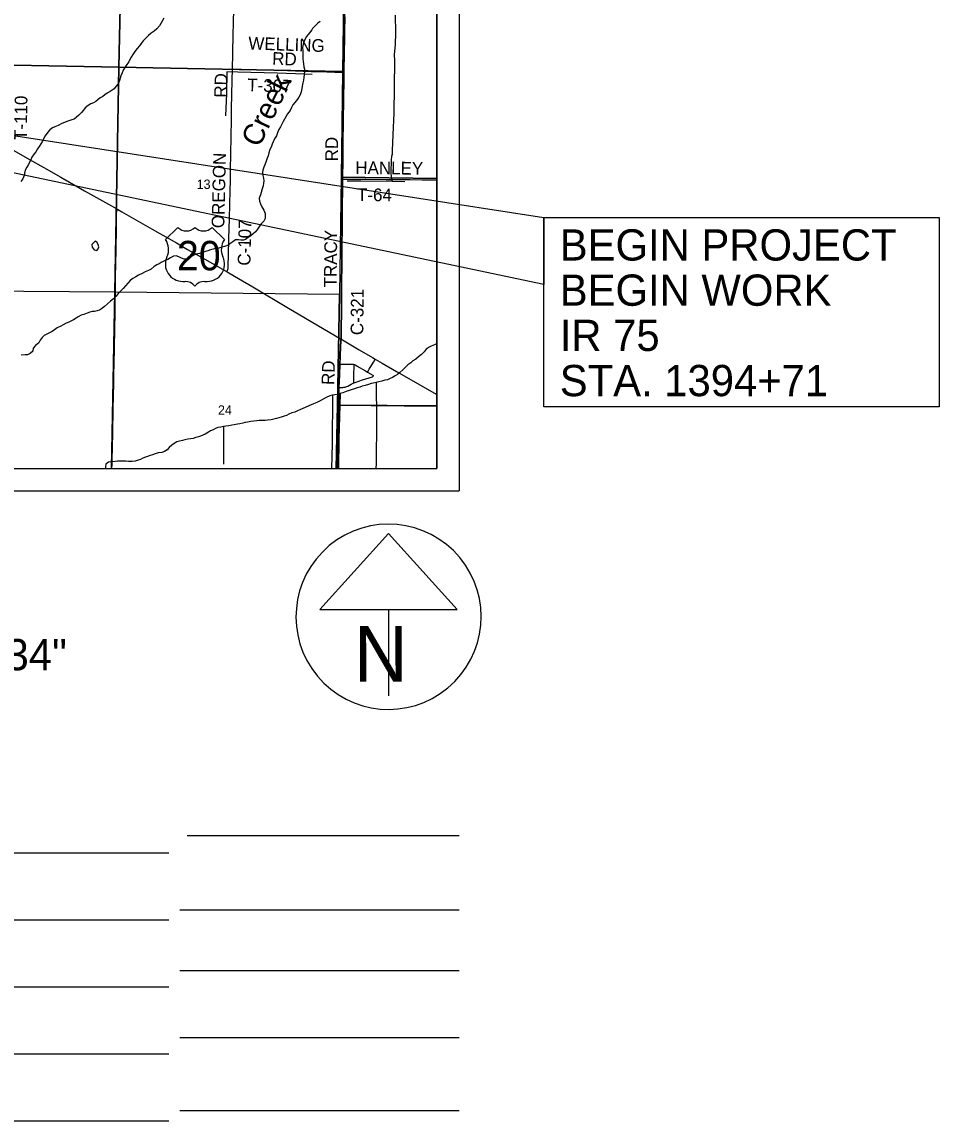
# Model space of a CAD drawing. Extents: x 0 to 34, y 0 to 22.
# Drawn here: x 7.043 to 11.15, y 11.177 to 16.1 of the extents above; entities that cross this region are included whole.
import ezdxf

# ---------------------------------------------------------------- set-up
doc = ezdxf.new("R2010")
doc.units = 0
for name, color, linetype in [('GM_X_Corporation', 7, 'Continuous'), ('GM_X_County_Road', 7, 'Continuous'), ('GM_X_County_Road_Text', 7, 'Continuous'), ('GM_X_Minor_Lake', 7, 'Continuous'), ('GM_X_Minor_River', 7, 'Continuous'), ('GM_X_Minor_River_Text', 7, 'Continuous'), ('GM_X_Section_Text', 7, 'Continuous'), ('GM_X_Township_Road', 7, 'Continuous'), ('GM_X_Township_Road_Text', 7, 'Continuous'), ('GM_X_US_Location', 7, 'Continuous'), ('GM_X_US_Route', 7, 'Continuous'), ('GM_X_US_Shield', 7, 'Continuous'), ('SH_Data', 7, 'Continuous'), ('SH_Text', 7, 'Continuous')]:
    doc.layers.add(name, color=color, linetype=linetype)

msp = doc.modelspace()

# ---------------------------------------------------------------- linework, layer by layer
at = {"layer": 'GM_X_Corporation'}
for points in [[(2.1, 14.1), (8.9, 14.1), (8.9, 20.9), (5.8906, 20.9)], [(8.4889, 16.1222), (8.4875, 16.0575), (8.4871, 16.0295), (8.4858, 15.9593), (8.4845, 15.8803), (8.4844, 15.8737), (8.4837, 15.8337), (8.4828, 15.7634), (8.4812, 15.6466), (8.4803, 15.5676), (8.4796, 15.5203), (8.4791, 15.4756), (8.4782, 15.4066), (8.4781, 15.3967), (8.4781, 15.3506), (8.4774, 15.2729), (8.4769, 15.2262), (8.4765, 15.1622), (8.4758, 15.1118), (8.4752, 15.0167), (8.4743, 14.924), (8.4737, 14.8656), (8.4731, 14.7904), (8.4726, 14.7381), (8.4723, 14.7071), (8.4716, 14.6802), (8.4711, 14.6716), (8.4707, 14.6634), (8.4699, 14.651), (8.4677, 14.5982), (8.4663, 14.568), (8.4663, 14.5671), (8.4642, 14.5205), (8.4627, 14.4863), (8.462, 14.4645), (8.462, 14.463), (8.4613, 14.4241), (8.4606, 14.3899), (8.4605, 14.3826), (8.9, 14.3789), (8.9, 20.9)], [(2.3741, 14.1), (8.4543, 14.1), (8.4553, 14.1598), (8.4566, 14.2158), (8.4581, 14.2655), (8.4592, 14.3153), (8.46, 14.3464), (8.4605, 14.3826), (8.4606, 14.3899), (8.4613, 14.4241), (8.462, 14.463), (8.462, 14.4645), (8.4627, 14.4863), (8.4642, 14.5205), (8.4663, 14.5671), (8.4663, 14.568), (8.4677, 14.5982), (8.4699, 14.651), (8.4707, 14.6634), (8.4711, 14.6716), (8.4716, 14.6802), (8.4723, 14.7071), (8.4726, 14.7381), (8.4731, 14.7904), (8.4737, 14.8656), (8.4743, 14.924), (8.4752, 15.0167), (8.4758, 15.1118), (8.4765, 15.1622), (8.4769, 15.2262), (8.4774, 15.2729), (8.4781, 15.3506), (8.4781, 15.3967), (8.4782, 15.4066), (8.4791, 15.4756), (8.4796, 15.5203), (8.4803, 15.5676), (8.4812, 15.6466), (8.4828, 15.7634), (8.4837, 15.8337), (8.4844, 15.8737), (8.4845, 15.8803), (8.4858, 15.9593), (8.4871, 16.0295), (8.4875, 16.0575), (8.4889, 16.1222)]]:
    msp.add_lwpolyline(points, dxfattribs=at)
for points in [[(6.4745, 16.9262), (7.4991, 16.9078), (7.4758, 15.8976), (6.4581, 15.916)], [(7.4991, 16.9078), (8.4956, 16.8828), (8.4859, 16.4125), (8.4788, 15.8782), (7.4758, 15.8976)], [(8.9, 15.399), (8.9, 16.4075), (8.4859, 16.4125), (8.4788, 15.8782), (8.4721, 15.4049)], [(6.4581, 15.916), (7.4758, 15.8976), (7.4587, 14.8897), (6.4397, 14.8975)], [(7.4758, 15.8976), (8.4788, 15.8782), (8.4721, 15.4049), (8.4652, 14.8797), (7.4587, 14.8897)], [(8.9, 14.3806), (8.9, 15.399), (8.4721, 15.4049), (8.4652, 14.8797), (8.4556, 14.3834)], [(6.4222, 14.1), (7.4432, 14.1), (7.4587, 14.8897), (6.4397, 14.8975)], [(7.4432, 14.1), (8.4504, 14.1), (8.4556, 14.3834), (8.4652, 14.8797), (7.4587, 14.8897)], [(8.4504, 14.1), (8.9, 14.1), (8.9, 14.3806), (8.4556, 14.3834)], [(8.4543, 14.1), (8.9, 14.1), (8.9, 14.3789), (8.4605, 14.3826), (8.46, 14.3464), (8.4592, 14.3153), (8.4581, 14.2655), (8.4566, 14.2158), (8.4553, 14.1598)]]:
    msp.add_lwpolyline(points, close=True, dxfattribs=at)
at = {"layer": 'GM_X_County_Road'}
for points in [[(7.9851, 15.8887), (7.9866, 15.9593), (7.9884, 16.0454), (7.9898, 16.0926), (7.9932, 16.2305), (7.9946, 16.2726), (7.9962, 16.3398), (7.9972, 16.3958)], [(8.4846, 15.8731), (8.4847, 15.8798), (8.4861, 15.9587), (8.4873, 16.029), (8.4877, 16.057), (8.4891, 16.1216), (8.49, 16.1701), (8.4912, 16.2267), (8.4918, 16.2553), (8.4924, 16.2975), (8.4928, 16.3274), (8.4933, 16.3653), (8.4935, 16.3796)], [(7.9613, 14.9807), (7.9638, 14.9881), (7.9648, 14.9911), (7.9655, 14.9948), (7.966, 14.9985), (7.9662, 15.0024), (7.9664, 15.0083), (7.9674, 15.0557), (7.9694, 15.1288), (7.9717, 15.219), (7.9747, 15.3448), (7.9759, 15.3877), (7.9768, 15.4449), (7.9778, 15.5009), (7.9793, 15.5947), (7.9805, 15.6532), (7.9813, 15.7128), (7.9826, 15.7731), (7.984, 15.8391), (7.9851, 15.8887)], [(8.4784, 15.3961), (8.4784, 15.406), (8.4793, 15.475), (8.4798, 15.5198), (8.4805, 15.567), (8.4814, 15.646), (8.4831, 15.7629), (8.4839, 15.8332), (8.4846, 15.8731)], [(8.4719, 14.6796), (8.4726, 14.7065), (8.4728, 14.7376), (8.4733, 14.7898), (8.4739, 14.8651), (8.4745, 14.9235), (8.4754, 15.0161), (8.476, 15.1113), (8.4767, 15.1616), (8.4772, 15.2257), (8.4776, 15.2723), (8.4783, 15.35), (8.4784, 15.3961)]]:
    msp.add_lwpolyline(points, dxfattribs=at)
at = {"layer": 'GM_X_Minor_Lake'}
msp.add_line((7.3863, 15.093), (7.3834, 15.1037), dxfattribs=at)
msp.add_lwpolyline([(7.3834, 15.1037), (7.3782, 15.114), (7.3711, 15.1179), (7.3562, 15.1033), (7.3571, 15.0911), (7.3657, 15.0789), (7.3774, 15.0768), (7.3839, 15.084), (7.3863, 15.093)], dxfattribs=at)
at = {"layer": 'GM_X_Minor_River'}
msp.add_line((8.9, 15.3795), (8.8999, 15.3795), dxfattribs=at)
for points in [[(7.6776, 16.1167), (7.6652, 16.0926), (7.6587, 16.0821), (7.6464, 16.0689), (7.6342, 16.0588), (7.6208, 16.0495), (7.609, 16.0394), (7.5971, 16.0274), (7.5853, 16.0147), (7.5764, 16.0038), (7.5687, 15.9929), (7.5591, 15.9805), (7.5487, 15.9673), (7.5395, 15.9541), (7.531, 15.9421), (7.526, 15.9323), (7.5206, 15.921), (7.5125, 15.9086), (7.504, 15.8965), (7.4963, 15.8841), (7.4908, 15.872), (7.4861, 15.8584), (7.483, 15.8478), (7.4794, 15.8372), (7.474, 15.8229), (7.4636, 15.8105), (7.4552, 15.8007), (7.4376, 15.7877), (7.4243, 15.7806), (7.4144, 15.7732), (7.4048, 15.7661), (7.393, 15.7594), (7.3835, 15.7527), (7.3728, 15.7437), (7.3629, 15.7381), (7.3508, 15.7326), (7.339, 15.7255), (7.3256, 15.7147), (7.3179, 15.7046), (7.3087, 15.6944), (7.298, 15.682), (7.2861, 15.6716), (7.2766, 15.6645), (7.2656, 15.6608), (7.2531, 15.6564), (7.2432, 15.6535), (7.2333, 15.6498), (7.2208, 15.6443), (7.2041, 15.6362), (7.1904, 15.6299), (7.1801, 15.6258), (7.1679, 15.6165), (7.158, 15.6056), (7.1468, 15.5891), (7.1391, 15.5766), (7.134, 15.5661), (7.1278, 15.5536), (7.1201, 15.5423), (7.1128, 15.531), (7.1051, 15.5186), (7.0978, 15.5088), (7.087, 15.4942), (7.0823, 15.4821), (7.0761, 15.4712), (7.0718, 15.4613), (7.0645, 15.4493), (7.0571, 15.4357), (7.0536, 15.4232), (7.0519, 15.4126), (7.0465, 15.3975), (7.0376, 15.3847)], [(8.3786, 16.1026), (8.3671, 16.094), (8.3557, 16.082), (8.3445, 16.07), (8.3411, 16.0647), (8.3299, 16.0505), (8.3173, 16.0354), (8.3111, 16.0237), (8.3048, 16.0094), (8.3013, 15.9996), (8.2992, 15.9848), (8.3009, 15.9711), (8.3012, 15.9593), (8.3003, 15.9472), (8.3008, 15.9339), (8.3018, 15.9225), (8.3028, 15.9119), (8.3053, 15.899), (8.3074, 15.8883), (8.3081, 15.8784), (8.3064, 15.8648), (8.3054, 15.8507), (8.3034, 15.8394), (8.3002, 15.8265), (8.297, 15.8121), (8.2953, 15.8015), (8.2925, 15.7864), (8.2882, 15.7735), (8.2824, 15.7634), (8.277, 15.7536), (8.2654, 15.7393), (8.2558, 15.728), (8.25, 15.7163), (8.2431, 15.7035), (8.2323, 15.6881), (8.2246, 15.6753), (8.2188, 15.6651), (8.2122, 15.6546), (8.2064, 15.6417), (8.2002, 15.6301), (8.1936, 15.6176), (8.1893, 15.6074), (8.1819, 15.5904), (8.1742, 15.5761), (8.1672, 15.5625), (8.1629, 15.552), (8.1586, 15.5387), (8.1531, 15.5282), (8.1488, 15.5142), (8.1448, 15.5006), (8.1405, 15.4892), (8.1362, 15.4756), (8.1303, 15.4605), (8.1253, 15.4492), (8.1209, 15.4356), (8.1201, 15.425)], [(8.7144, 16.1299), (8.7149, 16.0524), (8.7146, 15.997), (8.7095, 15.9546), (8.7114, 15.9257), (8.7079, 15.6912), (8.7029, 15.5964), (8.7004, 15.522), (8.6999, 15.508), (8.6982, 15.497), (8.6961, 15.4815), (8.6959, 15.4618), (8.6949, 15.447), (8.6946, 15.4246), (8.6963, 15.4067), (8.7013, 15.385)], [(8.343, 15.8647), (8.3075, 15.8663), (8.1859, 15.8697), (8.0088, 15.875), (7.9597, 15.876), (7.9581, 15.7792), (7.9549, 15.6787)], [(8.1201, 15.425), (8.1214, 15.4121), (8.1243, 15.3999), (8.126, 15.3881), (8.1251, 15.3782), (8.1231, 15.3654), (8.1191, 15.3529), (8.1136, 15.3366), (8.1104, 15.3249), (8.1057, 15.3106), (8.1059, 15.2965), (8.1111, 15.2851), (8.1173, 15.2713), (8.1262, 15.2568), (8.1313, 15.2419), (8.1322, 15.2298), (8.1314, 15.2199), (8.1259, 15.2082), (8.114, 15.1958), (8.1063, 15.1845), (8.0982, 15.171), (8.0883, 15.1593), (8.0779, 15.1507), (8.0669, 15.1425), (8.0554, 15.1347), (8.0436, 15.125), (8.0341, 15.1217), (8.0224, 15.1222), (8.0119, 15.1243), (7.999, 15.124), (7.9876, 15.1143), (7.9739, 15.1058), (7.9643, 15.0987), (7.9495, 15.0939), (7.9374, 15.0903), (7.9241, 15.0866), (7.9101, 15.0845), (7.8991, 15.0816), (7.8877, 15.0784), (7.8752, 15.0744), (7.8639, 15.0718), (7.8513, 15.0674), (7.8381, 15.0631), (7.8225, 15.0595), (7.8096, 15.0539), (7.7963, 15.045), (7.783, 15.0383), (7.7697, 15.0377), (7.7573, 15.0417), (7.7457, 15.0475), (7.7333, 15.0519), (7.7208, 15.0505), (7.7082, 15.0434), (7.6957, 15.0356), (7.6816, 15.0301), (7.6668, 15.022), (7.6565, 15.0164), (7.647, 15.0116), (7.634, 15.0045), (7.621, 14.9925), (7.61, 14.9866), (7.5948, 14.9807), (7.5808, 14.9737), (7.5652, 14.9655), (7.5522, 14.9577), (7.5385, 14.9503), (7.5267, 14.9414), (7.5175, 14.9301), (7.5067, 14.9181), (7.4956, 14.9065), (7.4864, 14.8963), (7.4742, 14.8836), (7.4638, 14.8712), (7.4523, 14.8603), (7.4386, 14.8491), (7.4264, 14.8379), (7.413, 14.8259), (7.3993, 14.8154), (7.3894, 14.8091), (7.3799, 14.8054), (7.3677, 14.8033), (7.3572, 14.8027), (7.3465, 14.7994), (7.3344, 14.795), (7.3192, 14.7891), (7.3075, 14.7859), (7.2949, 14.7784), (7.2854, 14.7725), (7.2736, 14.765), (7.2622, 14.7595), (7.2519, 14.7551), (7.2412, 14.7499), (7.2279, 14.7428), (7.2169, 14.7373), (7.2006, 14.7295), (7.188, 14.7206), (7.1781, 14.7139), (7.1667, 14.7079), (7.1541, 14.7016), (7.1423, 14.6953), (7.1328, 14.686)], [(8.7568, 15.384), (8.7013, 15.385), (8.56, 15.3868), (8.4988, 15.3861)], [(7.1328, 14.686), (7.1243, 14.6747), (7.1177, 14.6623), (7.1028, 14.6507), (7.0928, 14.6379), (7.0908, 14.625), (7.0801, 14.6153), (7.0672, 14.6094), (7.0566, 14.608), (7.0392, 14.6071)], [(8.9, 14.6589), (8.8897, 14.654), (8.8753, 14.6477), (8.8658, 14.6425), (8.8532, 14.6347), (8.8436, 14.622), (8.8317, 14.61), (8.8191, 14.5995), (8.8061, 14.5898), (8.7936, 14.5812), (8.7836, 14.5734), (8.771, 14.564), (8.7599, 14.5528), (8.7481, 14.5408)], [(8.7481, 14.5408), (8.7355, 14.5296), (8.724, 14.5202), (8.7141, 14.5143), (8.7016, 14.5072), (8.6917, 14.5028), (8.6791, 14.4973), (8.6681, 14.4947), (8.6545, 14.4915), (8.6412, 14.4875), (8.6295, 14.4846), (8.6162, 14.4817), (8.6064, 14.48), (8.5939, 14.4756), (8.5798, 14.4719), (8.5669, 14.4683), (8.5563, 14.4646), (8.5438, 14.4603), (8.532, 14.4558), (8.5176, 14.4515), (8.504, 14.4475), (8.4945, 14.4438), (8.4804, 14.439), (8.4675, 14.4354), (8.4543, 14.4314), (8.4433, 14.4296), (8.4331, 14.4275), (8.4217, 14.4246), (8.405, 14.4172), (8.3913, 14.4098), (8.3776, 14.402), (8.3635, 14.3953), (8.3483, 14.3891), (8.3384, 14.3843), (8.3274, 14.3799), (8.3111, 14.3729), (8.3004, 14.3684), (8.2902, 14.3636), (8.2765, 14.3581), (8.2643, 14.3526), (8.2507, 14.3482), (8.2374, 14.3423), (8.2271, 14.3375), (8.2173, 14.3342), (8.204, 14.329), (8.1926, 14.3265), (8.182, 14.3236), (8.1702, 14.3207), (8.1585, 14.3182), (8.1422, 14.3162), (8.1313, 14.3148), (8.1056, 14.3151), (8.0946, 14.3137), (8.0681, 14.3103), (8.053, 14.3078), (8.0424, 14.3056), (8.0314, 14.3027), (8.0181, 14.2999), (8.0075, 14.2977), (7.9931, 14.2956), (7.9829, 14.2935), (7.9693, 14.291), (7.9564, 14.2889), (7.945, 14.2879), (7.9333, 14.2854), (7.92, 14.2825), (7.909, 14.2792), (7.8988, 14.2729), (7.8877, 14.2677), (7.8782, 14.2618), (7.8638, 14.2532), (7.8524, 14.2484), (7.8429, 14.2448), (7.833, 14.2415), (7.822, 14.2382), (7.8095, 14.2342), (7.7989, 14.232), (7.7853, 14.2303), (7.772, 14.2278), (7.7618, 14.2253), (7.7478, 14.2221), (7.736, 14.2192), (7.7238, 14.2117), (7.7143, 14.2039), (7.7017, 14.1934), (7.6929, 14.1837), (7.681, 14.1751), (7.6689, 14.1711), (7.653, 14.1694), (7.6386, 14.1654), (7.6268, 14.161), (7.617, 14.1581), (7.6052, 14.1536), (7.5957, 14.15), (7.5847, 14.1463), (7.5729, 14.1404), (7.5627, 14.1363), (7.5494, 14.132), (7.5369, 14.1306), (7.5195, 14.1304), (7.5082, 14.1317)], [(8.6295, 14.4846), (8.6311, 14.3168), (8.6282, 14.1226), (8.6279, 14.1)], [(8.4331, 14.4275), (8.4313, 14.2097), (8.4288, 14.1)], [(8.4675, 14.4354), (8.4622, 14.2317), (8.4596, 14.1)], [(7.945, 14.2879), (7.9451, 14.119)], [(7.5082, 14.1317), (7.4946, 14.1326), (7.484, 14.1324), (7.4708, 14.1318), (7.4598, 14.1308), (7.4428, 14.1295), (7.43, 14.1278), (7.4189, 14.1196), (7.4168, 14.1074), (7.4167, 14.1)]]:
    msp.add_lwpolyline(points, dxfattribs=at)
at = {"layer": 'GM_X_Township_Road'}
for points in [[(7.9851, 15.8887), (7.9945, 15.8887), (8.0257, 15.8887), (8.1364, 15.8857), (8.2318, 15.8829), (8.3371, 15.8784), (8.408, 15.8759), (8.4434, 15.8746), (8.4782, 15.8734), (8.4846, 15.8731)], [(8.4784, 15.3961), (8.5179, 15.396), (8.5832, 15.3954), (8.6733, 15.3945), (8.7256, 15.3942), (8.7809, 15.3936), (8.8356, 15.3929), (8.8766, 15.3925), (8.9, 15.3921)], [(7.4457, 14.1), (7.446, 14.1197), (7.4464, 14.1415), (7.4475, 14.1937), (7.449, 14.2602), (7.4511, 14.3665), (7.4537, 14.4822), (7.4545, 14.5195), (7.4558, 14.5692), (7.4567, 14.637), (7.4583, 14.7271), (7.4597, 14.7955), (7.46, 14.8328), (7.4604, 14.8575), (7.461, 14.8862), (7.4614, 14.9024), (7.4622, 14.9683), (7.4631, 15.0056), (7.4643, 15.0895), (7.4657, 15.1679), (7.4659, 15.2015), (7.4661, 15.2288), (7.4664, 15.2462), (7.4665, 15.248), (7.4668, 15.2497), (7.4672, 15.2512), (7.4676, 15.2526), (7.4691, 15.2569), (7.4704, 15.2605)], [(8.4665, 14.5674), (8.4679, 14.5976), (8.4701, 14.6504), (8.4709, 14.6629), (8.4714, 14.671), (8.4719, 14.6796)], [(8.59, 14.5313), (8.5927, 14.5359), (8.5981, 14.5449), (8.617, 14.5762), (8.6209, 14.5825), (8.6251, 14.5894)], [(8.4622, 14.4625), (8.4623, 14.464), (8.4629, 14.4858), (8.4644, 14.5199), (8.4665, 14.5665), (8.4665, 14.5674)], [(8.4665, 14.5674), (8.4775, 14.5672), (8.4873, 14.567), (8.5237, 14.5663), (8.526, 14.5662), (8.528, 14.5658), (8.5306, 14.565), (8.5315, 14.5647)], [(8.529, 14.4826), (8.5289, 14.4876), (8.5288, 14.4913), (8.5295, 14.53), (8.53, 14.5471), (8.5305, 14.5546), (8.531, 14.5595), (8.5315, 14.5647)], [(8.5315, 14.5647), (8.5348, 14.5634), (8.5376, 14.5621), (8.5438, 14.5587), (8.5805, 14.5369), (8.59, 14.5313)], [(8.59, 14.5313), (8.6136, 14.5175), (8.6144, 14.5168), (8.6148, 14.516), (8.6151, 14.5152), (8.6153, 14.5143), (8.6153, 14.5136)], [(8.4622, 14.4625), (8.4669, 14.4626), (8.4798, 14.4631), (8.4836, 14.4635), (8.4868, 14.464), (8.49, 14.4646), (8.4933, 14.4656), (8.4972, 14.467), (8.502, 14.4691), (8.5177, 14.4773), (8.5262, 14.4814), (8.529, 14.4826)], [(8.529, 14.4826), (8.5301, 14.4831), (8.5344, 14.4846), (8.568, 14.4961), (8.6126, 14.5105), (8.6136, 14.511), (8.6141, 14.5114), (8.6146, 14.512), (8.6151, 14.5126), (8.6153, 14.5136)], [(8.4615, 14.4225), (8.4615, 14.4236), (8.4622, 14.4625)], [(8.4545, 14.1), (8.4556, 14.1593), (8.4569, 14.2152), (8.4583, 14.265), (8.4594, 14.3147), (8.4602, 14.3458), (8.4607, 14.3811)], [(8.4607, 14.3811), (8.4607, 14.382), (8.4608, 14.3893), (8.4615, 14.4225)]]:
    msp.add_lwpolyline(points, dxfattribs=at)
at = {"layer": 'GM_X_US_Route'}
for points in [[(6.9613, 15.5488), (7.0266, 15.5116), (7.0758, 15.4836), (7.1403, 15.4473), (7.216, 15.4043), (7.323, 15.344), (7.3895, 15.3064), (7.4295, 15.2838), (7.4704, 15.2605)], [(7.4704, 15.2605), (7.4905, 15.249), (7.6258, 15.1719), (7.6598, 15.1524), (7.6868, 15.137), (7.7343, 15.1099), (7.7845, 15.0812), (7.8408, 15.0495), (7.8965, 15.0178), (7.9613, 14.9807)], [(7.9613, 14.9807), (7.9688, 14.9764), (8.0129, 14.9508), (8.0772, 14.9129), (8.137, 14.8773), (8.1773, 14.8537), (8.2291, 14.8229), (8.3127, 14.7737), (8.4719, 14.6796)], [(8.4719, 14.6796), (8.4786, 14.6756), (8.5531, 14.6317), (8.6125, 14.5967), (8.6251, 14.5894)], [(8.6251, 14.5894), (8.6559, 14.5712), (8.7194, 14.5344), (8.7955, 14.4909), (8.8657, 14.4507), (8.9, 14.4309)]]:
    msp.add_lwpolyline(points, dxfattribs=at)
at = {"layer": 'GM_X_US_Shield'}
for p, q in [((7.7406, 15.1796), (7.6856, 15.1247)), ((7.9493, 15.1247), (7.8944, 15.1796)), ((7.7626, 14.9379), (7.7735, 14.9379)), ((7.8614, 14.9379), (7.8724, 14.9379))]:
    msp.add_line(p, q, dxfattribs=at)
for centre, radius, start, end in [((7.779, 15.2188), 0.0549, 225.573, 314.427), ((7.8559, 15.2188), 0.0549, 225.573, 314.427), ((7.6227, 15.0806), 0.0769, 334.5471, 35.0009), ((8.0123, 15.0806), 0.0769, 144.9991, 205.4529), ((7.7617, 15.0148), 0.0769, 154.8319, 270.6383), ((7.8733, 15.0148), 0.0769, 269.3617, 25.1681), ((7.7735, 14.883), 0.0549, 36.8699, 90), ((7.8614, 14.883), 0.0549, 90, 143.1301)]:
    msp.add_arc(centre, radius, start, end, dxfattribs=at)
at = {"layer": 'SH_Data'}
for p, q in [((9, 21), (9, 14)), ((9, 21), (9, 14)), ((8.9, 20.9), (8.9, 14.1)), ((8.9, 20.9), (8.9, 14.1)), ((2.1, 14.1), (8.9, 14.1)), ((2.1, 14.1), (8.9, 14.1)), ((2, 14), (9, 14)), ((2, 14), (9, 14)), ((8.6845, 13.8091), (8.3769, 13.4678)), ((8.9921, 13.4678), (8.6845, 13.8091)), ((8.3769, 13.4678), (8.9921, 13.4678)), ((8.6845, 13.4678), (8.6845, 13.0811)), ((8.6845, 13.4353), (8.6845, 13.4353)), ((8.6845, 13.4353), (8.6845, 13.4353)), ((7.7827, 12.4553), (9, 12.4553)), ((7.7, 12.3767), (4.8937, 12.3767)), ((9, 12.1207), (7.75, 12.1207)), ((7.7, 12.0767), (4.3895, 12.0767)), ((9, 11.8491), (7.75, 11.8491)), ((7.7, 11.7767), (3.8854, 11.7767)), ((9, 11.5491), (7.75, 11.5491)), ((7.7, 11.4767), (3.6448, 11.4767)), ((7.7, 11.1767), (5.0782, 11.1767)), ((9, 11.2223), (7.75, 11.2223))]:
    msp.add_line(p, q, dxfattribs=at)
msp.add_arc((8.6845, 13.4353), 0.4148, 129.7798, 129.7633, dxfattribs=at)
at = {"layer": 'SH_Text'}
for points in [[(3.9929, 16.0574), (9.3797, 15.2243), (9.3797, 14.9242)], [(9.3797, 15.2243), (11.1496, 15.2243), (11.1496, 14.3756), (9.3797, 14.3756)]]:
    msp.add_lwpolyline(points, close=True, dxfattribs=at)

# ---------------------------------------------------------------- texts
at = {"layer": 'GM_X_County_Road_Text'}
for s, rotation, p in [('RD', 88.525, (7.9601, 15.7599)), ('RD', 89.5098, (8.4576, 15.4751)), ('OREGON', 88.6851, (7.9485, 15.1757)), ('C-107', 88.6234, (8.0654, 15.0075)), ('TRACY', 89.3942, (8.4518, 14.9107)), ('C-321', 89.4481, (8.5712, 14.6968))]:
    msp.add_text(s, height=0.05682, rotation=rotation, dxfattribs=at).set_placement(p)
at = {"layer": 'GM_X_Minor_River_Text'}
msp.add_text('Creek', height=0.09476, rotation=64.1958, dxfattribs=at).set_placement((8.1051, 15.5333))
at = {"layer": 'GM_X_Section_Text'}
for s, p in [('13', (7.825, 15.352)), ('24', (7.9204, 14.3406))]:
    msp.add_text(s, height=0.04186, rotation=0, dxfattribs=at).set_placement(p)
at = {"layer": 'GM_X_Township_Road_Text'}
for s, rotation, p in [('WELLING', 358.0355, (8.0557, 15.9768)), ('RD', 358.0243, (8.1626, 15.9084)), ('T-307', 358.0347, (8.0508, 15.79)), ('T-110', 89.1704, (7.0644, 15.5709)), ('HANLEY', 359.3408, (8.5352, 15.419)), ('T-64', 359.6432, (8.5431, 15.2975)), ('RD', 88.027, (8.441, 14.4729))]:
    msp.add_text(s, height=0.05682, rotation=rotation, dxfattribs=at).set_placement(p)
at = {"layer": 'GM_X_US_Location'}
for s in ['0', '/']:
    msp.add_text(s, height=0.000189, dxfattribs=at).set_placement((7.8174, 15.0522))
msp.add_text('20', height=0.000189, rotation=0, dxfattribs=at).set_placement((7.7783, 15.013))
at = {"layer": 'GM_X_US_Shield'}
msp.add_text('20', height=0.13184, dxfattribs=at).set_placement((7.7366, 14.9873))
at = {"layer": 'SH_Data'}
msp.add_text('N', height=0.25, dxfattribs=at).set_placement((8.5292, 13.144))
at = {"layer": 'SH_Text'}
for s, p in [('BEGIN PROJECT', (9.4511, 15.031)), ('BEGIN WORK', (9.4511, 14.8285)), ('IR 75', (9.4511, 14.626)), ('STA. 1394+71', (9.4511, 14.4235)), ('LATITUDE:  41°33\'23"     LONGITUDE:  83°35\'34"', (3.071, 13.1959))]:
    msp.add_text(s, height=0.14, dxfattribs=at).set_placement(p)

doc.saveas('drawing.dxf')
